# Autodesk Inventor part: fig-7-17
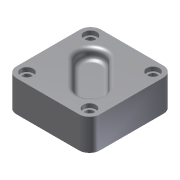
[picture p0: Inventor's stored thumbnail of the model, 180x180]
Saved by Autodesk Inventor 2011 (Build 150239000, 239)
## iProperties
Shininess: 77.0
Angle Display Precision: 2
Document Length Units: 11269
Document Angle Units: 11279
Document Time Units: 11290
Document Mass Units: 11283
Document Length Units Precision: 3
Document Angle Units Precision: 2
Created: 2001-12
Part Number: fig-7-17
Document SubType Name: Modeling
Designer: Renu Muthoo
Density: 1 g/cm^3
Density: 0.0
Volumn: 0.0
Area: 0.0
PropertySet Name: Model Information
Control State: 0
Master: False
Checked Out: False
Author: Renu Muthoo
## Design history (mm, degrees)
sketch "Sketch1"
  geometry: L1 (-20, 20)-(20, 20); L2 (20, 20)-(20, -20.5); L3 (20, -20.5)-(-20, -20.5); L4 (-20, -20.5)-(-20, 20); 1 further point
  constraints: 8 end point, 2 parallel, 1 horizontal, 1 perpendicular, 1 other
  dimensions: "d0" = 40 distance of L1.start L1.end; "d1" = 40.5 distance of L3.end L1.start; "d100" = 20 distance from line of L4 point (0, 0); "d101" = 20 distance from line of L1 point (0, 0)
extrude "Extrusion1" new body sketch "Sketch1" distance "d2" = 15; taper "d3" = 0 deg
workplane "Work Plane1"
workplane "Work Plane2"
workplane "Work Plane3"
fillet "Fillet1" dims "d32" = 5
hole "Hole3" diameter "d66" = 4; stored, may be unused: countersink angle "d70" = 90 deg, drill point angle "d72" = 118 deg; dims "d64" = 10, "d65" = 10, "d67" = 6, "d68" = 6, "d69" = 2, "d71" = 8
hole "Hole4" diameter "d75" = 4; stored, may be unused: countersink angle "d79" = 90 deg, drill point angle "d81" = 118 deg; dims "d73" = 10, "d74" = 10, "d76" = 6, "d77" = 6, "d78" = 2, "d80" = 8
hole "Hole5" diameter "d84" = 4; stored, may be unused: countersink angle "d88" = 90 deg, drill point angle "d90" = 118 deg; dims "d82" = 10, "d83" = 10, "d85" = 6, "d86" = 6, "d87" = 2, "d89" = 8
hole "Hole6" diameter "d93" = 4; stored, may be unused: countersink angle "d97" = 90 deg, drill point angle "d99" = 118 deg; dims "d91" = 10, "d92" = 10, "d94" = 6, "d95" = 6, "d96" = 2, "d98" = 8
fillet "Fillet2" dims "d61" = 2
body "Solid1"
sketch "Sketch8"
  geometry: L1 (-9.844, 1.64)-(1.983, -10.187); L2 (10.469, -1.701)-(-1.358, 10.126); A1 r 6 centre (-5.601, 5.883) between (-1.358, 10.126) and (-9.844, 1.64); A2 r 6 centre (6.226, -5.944) between (1.983, -10.187) and (10.469, -1.701)
  constraints: 4 end point, 4 point on circle, 4 tangent, 2 centre point, 1 parallel
  dimensions: "d29" = 6 radius of A2
extrude "Extrusion2" cut sketch "Sketch8" distance "d30" = 5; taper "d31" = 0 deg
